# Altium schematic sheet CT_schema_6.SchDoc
size 278 x 170 mm
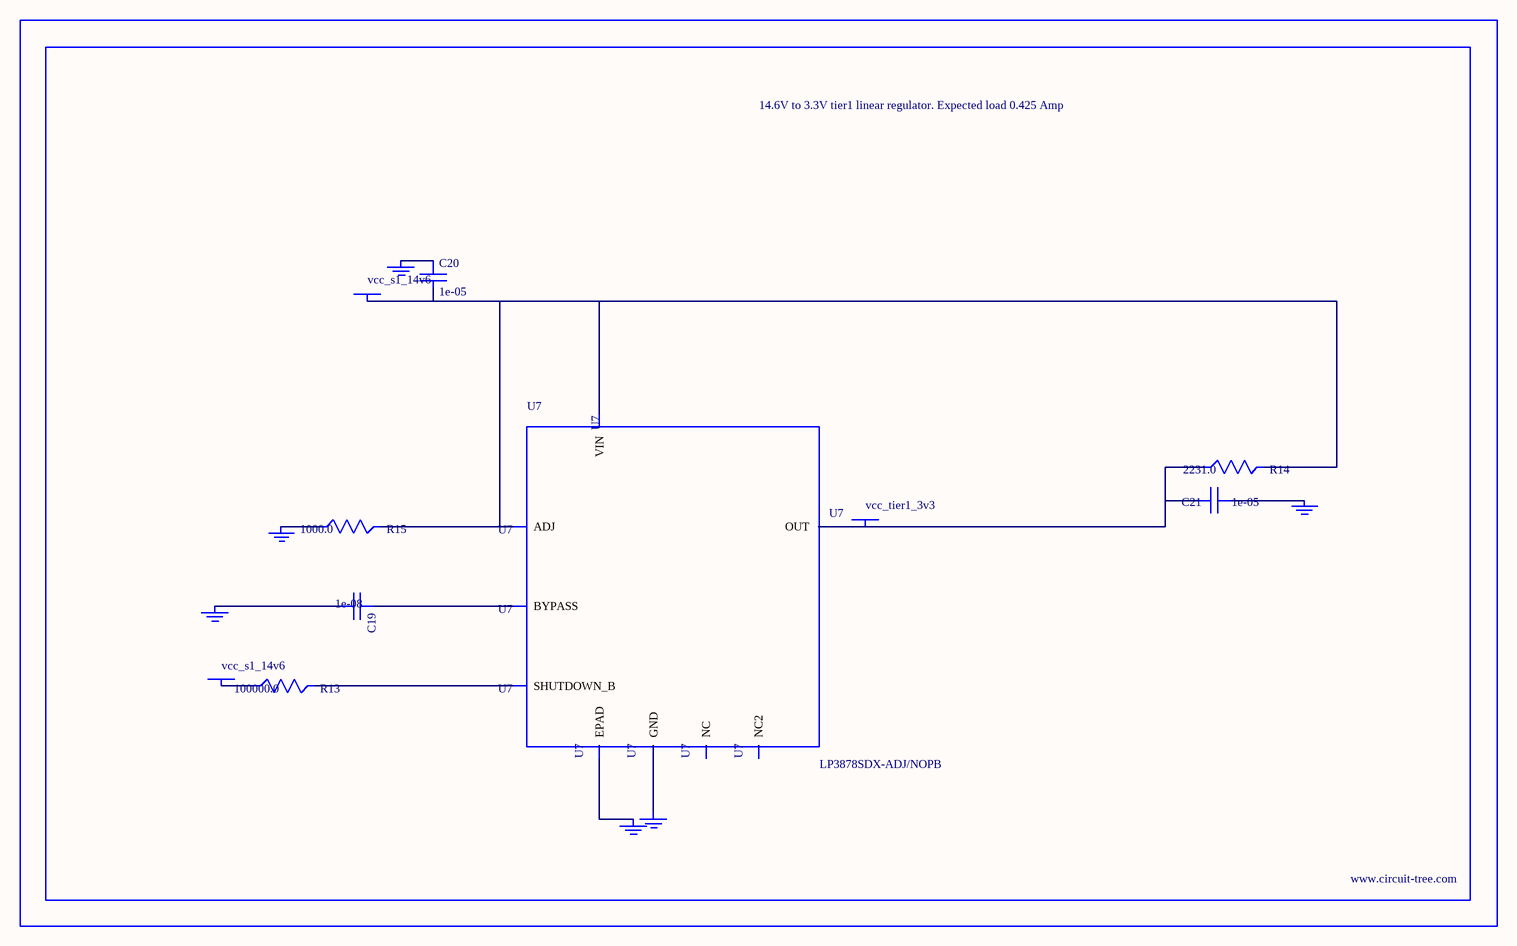
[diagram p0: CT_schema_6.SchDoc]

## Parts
BORDER5  (no value)
C19  1e-08  [C0402]
C20  1e-05  [C1210]
C21  1e-05  [C1210]
GND_INSTANCE_5_0  (no value)
GND_INSTANCE_5_1  (no value)
GND_INSTANCE_5_2  (no value)
GND_INSTANCE_5_3  (no value)
GND_INSTANCE_5_4  (no value)
GND_INSTANCE_5_5  (no value)
POWER_INSTANCE_5_0  vcc_s1_14v6
POWER_INSTANCE_5_1  vcc_s1_14v6
POWER_INSTANCE_5_2  vcc_tier1_3v3
R13  100000.0  [R0603]
R14  2231.0  [R0603]
R15  1000.0  [R0603]
U7  LP3878SDX-ADJ/NOPB  [WSON-8]

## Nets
NetC19_1: C19.1 U7.1(BYPASS)
NetC19_2: C19.2 GND_INSTANCE_5_0.0(GND)
NetC20_1: C20.1 GND_INSTANCE_5_1.0(GND)
NetC20_2: C20.2 POWER_INSTANCE_5_0.0(PWR) R14.2 R15.2 U7.4(VIN) U7.6(ADJ)
NetC21_1: C21.1 GND_INSTANCE_5_2.0(GND)
NetC21_2: C21.2 POWER_INSTANCE_5_2.0(PWR) R14.1 U7.5(OUT)
NetGND_INSTANCE_5_3_0: GND_INSTANCE_5_3.0(GND) R15.1
NetGND_INSTANCE_5_4_0: GND_INSTANCE_5_4.0(GND) U7.PAD(EPAD)
NetGND_INSTANCE_5_5_0: GND_INSTANCE_5_5.0(GND) U7.3(GND)
NetPOWER_INSTANCE_5_1_0: POWER_INSTANCE_5_1.0(PWR) R13.1
NetR13_2: R13.2 U7.8(SHUTDOWN_B)

Not connected (* = marked no-connect by the designer): U7 2(NC) 7(NC2)

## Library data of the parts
BORDER5 = BORDER_PAGE5
C19 = C0402C103K3RAC
C20 = C1210C106K5PACTU
C21 = GRM32DR61E106MA12L
GND_INSTANCE_5_0-GND_INSTANCE_5_5 = GND
POWER_INSTANCE_5_0-POWER_INSTANCE_5_2 = PWR
R13 = RC0603JR-07100KL
R14 = R14
R15 = RC0603JR-071KL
